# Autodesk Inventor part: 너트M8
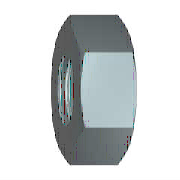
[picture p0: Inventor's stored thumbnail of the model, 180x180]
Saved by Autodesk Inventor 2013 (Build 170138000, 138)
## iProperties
Created: 2009-02
Part Number: 너트M8
Material: 강, 연강
Description: 6각 너트 및 6각 가는 너트
Document SubType Name: Modeling
Standard: KS B 1012
Designer: KYOUNG IL JANG
Standards Organization: KS
Language: ko-KR
Size Designation: C M8
Categories: <MemberInstance><Categories><Category DisplayName="조임쇠" InternalName="e4da775c-781d-43d5-af7c-5136215cf5a6" Mnemonic="FSTN"><Category DisplayName="너트" InternalN
Density: 7.86 g/cm^3
Vendor: CBT Solutions
Mass: 6.84944 g
Surface Area: 7.1883 cm^2
Volume: 0.87143 cm^3
Company: 한국ATC센터
IsCustomPart: 0
Author: KYOUNG IL JANG
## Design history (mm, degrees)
sketch "스케치1"
  geometry: L1 (-7.506, 0)-(-3.753, 6.5); L2 (-3.753, 6.5)-(3.753, 6.5); L3 (3.753, 6.5)-(7.506, 0); L4 (7.506, 0)-(3.753, -6.5); L5 (3.753, -6.5)-(-3.753, -6.5); L6 (-3.753, -6.5)-(-7.506, 0); 2 further points
  constraints: 12 end point, 1 coincident, 1 horizontal, 11 other
  dimensions: "d0" = 15.01111 distance of L3.end L1.start (= 1.1547 x SW)
extrude "본체" new body sketch "스케치1" distance "d1" = 7.9 (= KOH); taper "d2" = 0 deg
sketch "스케치2"
  geometry: L1 (0, 3.753)-(0, 7.506) reference; L2 (0, 7.506)-(7.9, 7.506) reference; L3 (7.9, 3.753)-(7.9, 7.506) reference; L4 (-1.58, 0)-(9.48, 0) reference; L5 (0.581, 7.506)-(0, 6.5); L6 (7.319, 7.506)-(7.9, 6.5)
  constraints: 4 end point, 4 point on line
  dimensions: "d3" = 30 deg angle of L1 L5 (= ANG1); "d4" = 30 deg angle of L3 L6 (= ANG2); "d5" = 13 diameter of L5.end L4 (= SW0); "d6" = 13 diameter of L6.end L4 (= SW01)
revolve "모따기1" sketch "스케치2" stored, may be unused: angle "d7" = 90 deg
sketch "스케치3"
  geometry: A1 r 6.5 centre (0, 0) between (-3.25, -5.629) and (3.25, -5.629) reference; 1 further point
  constraints: 1 coincident
hole "스레드" sketch "스케치3" at (0, 0) diameter "d25" = 6.647; stored, may be unused: countersink angle "d29" = 82 deg, drill point angle "d31" = 118 deg; dims "d26" = 6, "d27" = 4, "d28" = 2, "d30" = 8
workaxis "Work Axis1"
workplane "Work Plane1"
body "Solid1"
chamfer "모따기2" distance "d8" = 0.67658 (= -0.5 x GD1 + 0.5 x NND); stored, may be unused: angle "d9" = 30 deg, second distance "d40" = 0.67658 (= -0.5 x GD1 + 0.5 x NND)
chamfer "모따기3" distance "d10" = 0.67658 (= -0.5 x GD1 + 0.5 x NND); stored, may be unused: angle "d11" = 30 deg, second distance "d41" = 0.67658 (= -0.5 x GD1 + 0.5 x NND)
other parameters: "ANG1" = 30 deg [user parameter; used in 1 equation term], "ANG2" = 30 deg [user parameter; used in 1 equation term], "NND" = 8 [user parameter; used in 4 equation terms], "KOH" = 7.9 [user parameter; used in 1 equation term], "SW" = 13 [user parameter; used in 4 equation terms], "SW0" = 13 (= SW) [user parameter; used in 1 equation term], "SW01" = 13 (= SW) [user parameter; used in 1 equation term], "GD1" = 6.64684 (computed from THREADDIA, PTC, TOA) [user parameter; used in 4 equation terms], "d13" = 0, "d14" = 0, "d39" = 0, "d42" = 0, "GUL" = 0.67658 (= 0.541266 x PTC) [user parameter], "TPU" = 8 (computed from PTC) [user parameter], "THREADDIA" = 8 [user parameter; used in 1 equation term], "TOA" = 30 deg [user parameter; used in 1 equation term], "PTC" = 1.25 [user parameter; used in 4 equation terms], "E0" = 15.015 (= 1.155 x SW) [user parameter], "GAL" = 0.67658 (= 0.541266 x PTC) [user parameter]
